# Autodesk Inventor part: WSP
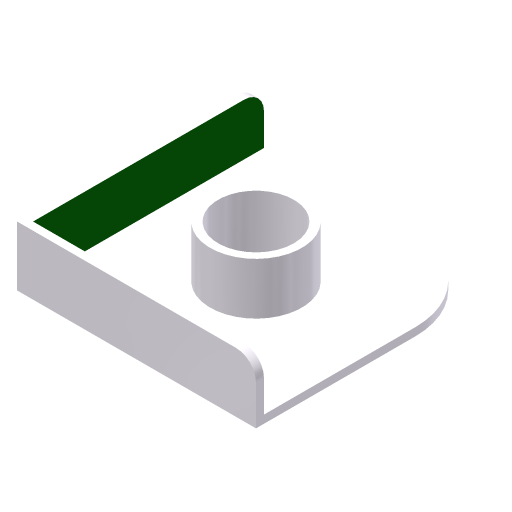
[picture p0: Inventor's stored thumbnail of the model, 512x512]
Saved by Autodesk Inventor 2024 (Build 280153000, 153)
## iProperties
Company: ATC
Shininess: 21.0
Length Units: 11269
Angle Units: 11279
Time Units: 11290
Mass Units: 11283
Length Display Precision: 3
Angle Display Precision: 2
Compacted: True
Created: 2023-03
Part Number: WSP
Document SubType Name: Modeling
Designer: Andrzej Jaskulski
Material: Kurs-AJ
Density: 1 g/cm^3
Mass: 11.2231 g
Surface Area: 118.487 cm^2
Volume: 11.2231 cm^3
Appearance: Kurs-AJ
Checked By: A.J.
Engr Approved By: Andrzej Jaskulski
Mfg Approved By: Andrzej Jaskulski
Authority: A.J.
Density: 0.0
Volumn: 0.0
Area: 0.0
PropertySet Name: Model Information
Control State: 0
Master: False
Checked Out: False
Title: A.J.: Kurs R2024-MEP
Author: Andrzej Jaskulski
Revision Number: 1/24
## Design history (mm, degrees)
sketch "Sketch1"
  geometry: L1 (0, 0)-(60, 0); L2 (60, 0)-(60, 60); L3 (60, 60)-(0, 60); L4 (0, 60)-(0, 0)
  constraints: 8 end point, 2 parallel, 1 horizontal, 1 perpendicular, 1 other
  dimensions: "d0" = 60 distance of L1.start L1.end (= x); "d1" = 60 distance of L1.end L2.end (= y)
extrude "Baza" new body sketch "Sketch1" distance "d2" = 15 (= h); taper "d3" = 0 deg
sketch "Sketch3"
  geometry: L1 (0, 0)-(0, 60) reference; L2 (60, 0)-(0, 0) reference; 1 further point
  dimensions: "d9" = 30 distance from line of L1 point (30, 30) (= Lx); "d10" = 30 distance from line of L2 point (30, 30) (= Ly)
hole "Otwór" sketch "Sketch3" diameter "d7" = 19; stored, may be unused: countersink angle "d18" = 60 deg, drill point angle "d20" = 118 deg; dims "d8" = 6, "d16" = 4, "d17" = 2, "d19" = 8
fillet "Zaokrąglenie1" dims "d4" = 20 (= d)
fillet "Zaokrąglenie2" dims "d5" = 5 (= 0.5 x r)
feature "Skorupa1" dims "d6" = 2
node "Bryła1"
node "Korpusy bryłowe"
node "Korpusy powierzchniowe"
other parameters: "x" = 60 [user parameter; used in 1 equation term], "y" = 60 [user parameter; used in 1 equation term], "h" = 15 [user parameter; used in 1 equation term], "Lx" = 30 [user parameter; used in 1 equation term], "Ly" = 30 [user parameter; used in 1 equation term], "L2" = 1 [user parameter]
